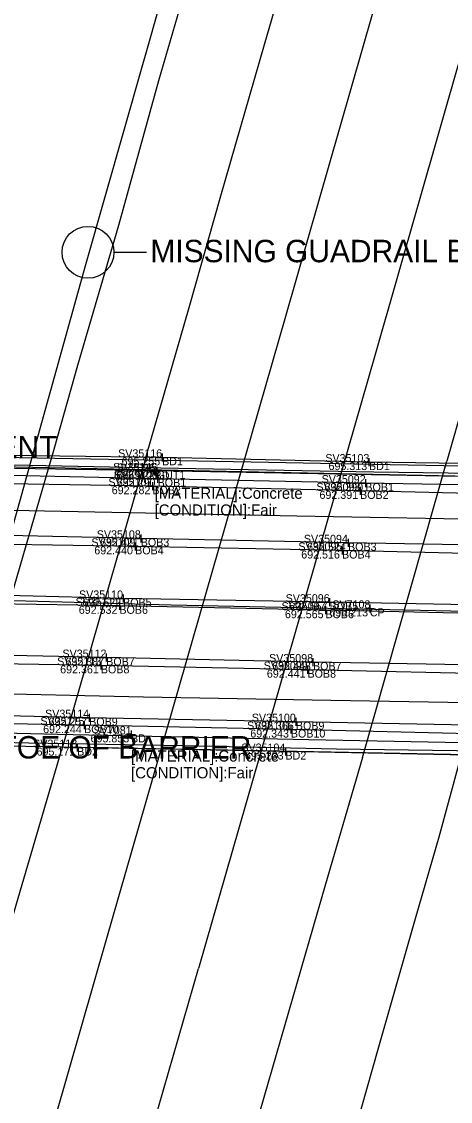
# Model space of a CAD drawing. Extents: x 1659932 to 1663108, y 619867 to 620611.
# Drawn here: x 1661299.3 to 1661352.9, y 620170.2 to 620305.2 of the extents above; entities that cross this region are included whole.
import ezdxf

# ---------------------------------------------------------------- set-up
doc = ezdxf.new("R2010")
doc.units = 0
for name, color, linetype in [('BR_X_Rail_Object', 7, 'Continuous'), ('BR_X_SV_Bottom_of_Beam', 7, 'Continuous'), ('BR_X_SV_Bottom_of_Beam_Text', 7, 'Continuous'), ('BR_X_SV_Deck_Top', 7, 'Continuous'), ('BR_X_SV_Deck_Top_Text', 7, 'Continuous'), ('PM_X_CL_Double_Solid', 7, 'Continuous'), ('PM_X_Edge_Line', 7, 'Continuous'), ('PM_X_Lane_Line', 7, 'Continuous'), ('PV_X_Curb', 7, 'Continuous'), ('PV_X_EOP', 7, 'Continuous'), ('RD_X_GR_Rt', 7, 'Continuous'), ('SC_Scratch6', 7, 'Continuous'), ('SV_X_Break_Lines', 7, 'Continuous'), ('SV_X_Shot_Marker', 7, 'Continuous'), ('SV_X_Text', 7, 'Continuous'), ('SV_X_Text_Comment', 7, 'Continuous'), ('SV_X_Text_Elevation', 7, 'Continuous'), ('SV_X_Text_Name', 7, 'Continuous')]:
    doc.layers.add(name, color=color, linetype=linetype)

msp = doc.modelspace()

# ---------------------------------------------------------------- linework, layer by layer
at = {"layer": 'BR_X_Rail_Object'}
for points in [[(1661456.59, 620247.69), (1661443.63, 620247.91), (1661428.53, 620248.27), (1661413.14, 620248.51), (1661400.82, 620248.72), (1661386.31, 620249), (1661374.13, 620249.21), (1661358.77, 620249.51), (1661343.2, 620249.8), (1661327.99, 620250.09), (1661312.41, 620250.4), (1661292.25, 620250.78)], [(1661292.27, 620249.91), (1661312.35, 620249.47), (1661327.66, 620249.2), (1661343.36, 620248.92), (1661358.83, 620248.69), (1661374.6, 620248.4), (1661387.62, 620248.08), (1661401.06, 620247.89), (1661413.42, 620247.71), (1661428.46, 620247.39), (1661443.69, 620247.11), (1661456.88, 620246.85)], [(1661277.09, 620215.16), (1661299.83, 620214.64), (1661320.76, 620214.23), (1661340.16, 620213.86), (1661357.27, 620213.54), (1661379.28, 620213.13), (1661397.22, 620212.74), (1661415.21, 620212.37), (1661433.51, 620212.02), (1661450.82, 620211.69)], [(1661450.15, 620212.16), (1661434.35, 620212.46), (1661415.69, 620212.76), (1661398.09, 620213.11), (1661378.82, 620213.5), (1661356.68, 620213.98), (1661338.69, 620214.25), (1661319.51, 620214.68), (1661300.2, 620215), (1661277.5, 620215.53)]]:
    msp.add_lwpolyline(points, dxfattribs=at)
at = {"layer": 'BR_X_SV_Bottom_of_Beam'}
for points in [[(1661517.58, 620243.01), (1661496.9, 620243.44), (1661470.92, 620243.84), (1661445.09, 620244.44), (1661419.15, 620244.95), (1661393.26, 620245.42), (1661367.36, 620245.92), (1661341.63, 620246.52), (1661315.65, 620247.11), (1661289.75, 620247.52), (1661264.38, 620248.32), (1661238.2, 620248.61)], [(1661523.4, 620243.85), (1661497.42, 620244.38), (1661471.69, 620244.95), (1661445.77, 620245.45), (1661419.9, 620245.97), (1661394.01, 620246.51), (1661368.15, 620247.03), (1661342.29, 620247.49), (1661316.31, 620248.04), (1661290.56, 620248.6), (1661264.65, 620249.03), (1661238.6, 620249.58)], [(1661521.26, 620236.36), (1661495.33, 620236.96), (1661469.49, 620237.51), (1661443.57, 620238), (1661417.71, 620238.51), (1661391.88, 620239.08), (1661365.99, 620239.56), (1661340.12, 620240.03), (1661314.2, 620240.59), (1661288.35, 620241.15), (1661262.48, 620241.61), (1661236.62, 620242.15)], [(1661520.6, 620235.45), (1661494.63, 620235.97), (1661468.71, 620236.38), (1661442.94, 620237), (1661417.1, 620237.51), (1661391.1, 620237.98), (1661365.2, 620238.45), (1661339.37, 620239.07), (1661313.5, 620239.59), (1661287.59, 620239.99), (1661261.72, 620240.63), (1661235.91, 620241.14)], [(1661519.08, 620228.95), (1661493.23, 620229.44), (1661467.37, 620230.03), (1661441.42, 620230.57), (1661415.6, 620231.07), (1661389.73, 620231.65), (1661363.82, 620232.13), (1661337.82, 620232.61), (1661311.99, 620233.08), (1661286.18, 620233.72), (1661260.33, 620234.13), (1661234.38, 620234.66)], [(1661518.51, 620227.98), (1661492.53, 620228.47), (1661466.56, 620228.95), (1661440.74, 620229.56), (1661414.82, 620230.07), (1661388.94, 620230.52), (1661363.07, 620231.02), (1661337.3, 620231.61), (1661311.53, 620232.16), (1661285.45, 620232.59), (1661259.59, 620233.14), (1661233.67, 620233.67)], [(1661516.94, 620221.49), (1661491.08, 620222.02), (1661465.19, 620222.58), (1661439.25, 620223.09), (1661413.44, 620223.61), (1661387.58, 620224.17), (1661361.7, 620224.66), (1661335.74, 620225.13), (1661309.88, 620225.69), (1661284.01, 620226.24), (1661258.16, 620226.7), (1661232.1, 620227.23)], [(1661516.25, 620220.54), (1661490.62, 620220.91), (1661464.53, 620221.45), (1661438.64, 620222.1), (1661412.71, 620222.61), (1661386.76, 620223.07), (1661360.95, 620223.56), (1661335.05, 620224.18), (1661309.21, 620224.72), (1661283.27, 620225.13), (1661257.54, 620225.69), (1661231.6, 620226.26)], [(1661514.76, 620214.06), (1661488.91, 620214.55), (1661463.02, 620215.15), (1661437.13, 620215.62), (1661411.26, 620216.17), (1661385.43, 620216.69), (1661359.54, 620217.18), (1661333.6, 620217.68), (1661307.75, 620218.18), (1661281.89, 620218.77), (1661255.86, 620219.28), (1661229.67, 620219.8)], [(1661514.07, 620213.08), (1661488.21, 620213.6), (1661462.26, 620214.04), (1661436.51, 620214.64), (1661410.52, 620215.17), (1661384.6, 620215.6), (1661358.81, 620216.08), (1661332.97, 620216.7), (1661307.11, 620217.25), (1661281.1, 620217.69), (1661255.32, 620218.27), (1661229.46, 620218.85)]]:
    msp.add_lwpolyline(points, dxfattribs=at)
at = {"layer": 'BR_X_SV_Deck_Top'}
for points in [[(1661524.15, 620246.52), (1661498.29, 620247.07), (1661472.43, 620247.6), (1661446.52, 620248.07), (1661420.55, 620248.6), (1661394.77, 620249.02), (1661368.93, 620249.74), (1661342.74, 620250.12), (1661316.87, 620250.71), (1661291.25, 620251.01), (1661265.13, 620251.8)], [(1661513.53, 620210.29), (1661487.66, 620211.1), (1661461.66, 620211.35), (1661435.63, 620211.89), (1661409.96, 620212.42), (1661383.84, 620212.93), (1661332.3, 620213.95), (1661306.25, 620214.44), (1661280.43, 620214.97), (1661254.73, 620215.77)]]:
    msp.add_lwpolyline(points, dxfattribs=at)
at = {"layer": 'PM_X_CL_Double_Solid'}
msp.add_lwpolyline([(1661546.99, 620228), (1661534.02, 620228.31), (1661515.7, 620228.67), (1661490.63, 620229.2), (1661465.72, 620229.57), (1661443.89, 620229.92), (1661424.27, 620230.22), (1661405.8, 620230.53), (1661384.67, 620230.88), (1661362.57, 620231.27), (1661341.51, 620231.74), (1661317.99, 620232.23), (1661293.69, 620232.89), (1661270.17, 620233.35), (1661246.4, 620233.83), (1661221.68, 620234.26), (1661205.71, 620234.62)], dxfattribs=at)
at = {"layer": 'PM_X_Edge_Line'}
for p, q in [((1661314.92, 620250.98), (1661304.26, 620213.97)), ((1661341.94, 620213.22), (1661352.49, 620250.24))]:
    msp.add_line(p, q, dxfattribs=at)
for points in [[(1661314.92, 620250.98), (1661320.24, 620269.45), (1661324.21, 620283.38), (1661329.68, 620302.28), (1661336.02, 620324.07), (1661342.92, 620348.04), (1661349.76, 620372.22), (1661357.79, 620400.47), (1661365.87, 620428.74), (1661375.17, 620461.08), (1661385.4, 620496.29), (1661395.58, 620531), (1661407.96, 620573.95), (1661414.41, 620596.94)], [(1661447.15, 620578.18), (1661442.08, 620560.71), (1661436.66, 620541.93), (1661430.96, 620522.04), (1661424.5, 620499.71), (1661417.8, 620476.46), (1661410.39, 620450.9), (1661399.15, 620411.88), (1661394.24, 620394.79), (1661380.03, 620345.6), (1661374.37, 620326.1), (1661366.48, 620299.21), (1661362.47, 620285.11), (1661357.43, 620267.56), (1661352.49, 620250.24)], [(1661550.12, 620239.2), (1661538.67, 620239.52), (1661512.09, 620240.18), (1661488.88, 620240.66), (1661465.84, 620241.07), (1661441.89, 620241.44), (1661414.82, 620241.89), (1661388.37, 620242.34), (1661361.28, 620242.85), (1661333.71, 620243.37), (1661302.17, 620244), (1661273.35, 620244.59), (1661246.42, 620245.13), (1661216.4, 620245.66), (1661208.5, 620245.81)], [(1661202.2, 620223.59), (1661213.11, 620223.27), (1661228.39, 620222.77), (1661259.55, 620222), (1661275.15, 620221.64), (1661292.52, 620221.27), (1661314.56, 620220.78), (1661337.97, 620220.36), (1661364.83, 620219.9), (1661379.25, 620219.63), (1661405.95, 620219.2), (1661427.48, 620218.87), (1661447.99, 620218.48), (1661471.4, 620218.02), (1661496.02, 620217.59), (1661519.24, 620217.2), (1661540.28, 620216.77), (1661543.97, 620216.72)], [(1661205.76, 619869.48), (1661211.13, 619888.81), (1661217.41, 619910.98), (1661224.34, 619935.2), (1661231.75, 619961.45), (1661235.51, 619974.89), (1661240.67, 619993.15), (1661247.93, 620018.65), (1661255.82, 620046.31), (1661265.01, 620078.44), (1661274.65, 620112.11), (1661283.8, 620143.93), (1661298.65, 620194.91), (1661304.26, 620213.97)], [(1661341.94, 620213.22), (1661337.31, 620197.39), (1661326.5, 620160.05), (1661314.91, 620119.7), (1661309.67, 620101.22), (1661301.86, 620073.85), (1661294.2, 620047.04), (1661286.06, 620018.73), (1661279.32, 619995.43), (1661269.93, 619963.07), (1661260.59, 619930.4), (1661255.64, 619912.95), (1661249.95, 619892.74), (1661243.97, 619871.61)]]:
    msp.add_lwpolyline(points, dxfattribs=at)
at = {"layer": 'PM_X_Lane_Line'}
for p, q in [((1661309.87, 620190.36), (1661332.33, 620268.36)), ((1661343.5, 620263.55), (1661321.42, 620186.85))]:
    msp.add_line(p, q, dxfattribs=at)
for points in [[(1661332.33, 620268.36), (1661343.26, 620306.38), (1661354.65, 620346.19), (1661365.24, 620383.52), (1661376.49, 620422.77), (1661387.47, 620460.99), (1661398.71, 620499.13), (1661410.08, 620538.06), (1661421.21, 620576.86)], [(1661431.96, 620570.3), (1661421.04, 620532.1), (1661410.7, 620495.6), (1661399.42, 620457.06), (1661388.16, 620417.77), (1661377.14, 620379.94), (1661365.7, 620340.36), (1661354.27, 620301.08), (1661343.5, 620263.55)], [(1661221.59, 619881.87), (1661232.5, 619920.16), (1661243.45, 619958.79), (1661254.55, 619998.19), (1661265.28, 620036.08), (1661276.49, 620075.34), (1661287.7, 620113.67), (1661298.9, 620152.14), (1661309.87, 620190.36)], [(1661233.25, 619878.6), (1661244.2, 619917.52), (1661254.62, 619954.7), (1661265.49, 619992.35), (1661276.71, 620030.87), (1661288.27, 620071), (1661299.13, 620109.41), (1661309.52, 620145.68), (1661321.42, 620186.85)]]:
    msp.add_lwpolyline(points, dxfattribs=at)
at = {"layer": 'PV_X_Curb'}
msp.add_lwpolyline([(1661523.34, 620245.12), (1661471.57, 620246.11), (1661446, 620246.6), (1661316.22, 620249.01), (1661290.79, 620249.44), (1661264.95, 620250.25), (1661238.71, 620250.79)], dxfattribs=at)
at = {"layer": 'PV_X_EOP'}
msp.add_line((1661292.37, 620214.09), (1661303.39, 620251.73), dxfattribs=at)
for points in [[(1661303.39, 620251.73), (1661306.32, 620262.23), (1661311.45, 620279.74), (1661316.46, 620297.78), (1661320.54, 620311.85)], [(1661354.07, 620212.76), (1661351.46, 620203.27), (1661348.5, 620193.03), (1661343.86, 620176.72), (1661338.34, 620157.33), (1661329.5, 620126.95), (1661323.43, 620105.42), (1661317.63, 620085.66), (1661309.75, 620058.02), (1661302.02, 620030.69), (1661292.65, 619998.31), (1661288.53, 619983.09), (1661284.46, 619969.78), (1661279.63, 619952.97), (1661274.63, 619935.67), (1661263.8, 619897.55), (1661258.1, 619878.27)]]:
    msp.add_lwpolyline(points, dxfattribs=at)
at = {"layer": 'RD_X_GR_Rt'}
msp.add_line((1661307.3, 620274.78), (1661286.56, 620200.56), dxfattribs=at)
msp.add_lwpolyline([(1661365.74, 620480.35), (1661358.38, 620454.11), (1661351.31, 620429.73), (1661342.87, 620400.4), (1661334.47, 620370.93), (1661319.26, 620316.75), (1661307.3, 620274.78)], dxfattribs=at)
at = {"layer": 'SC_Scratch6'}
msp.add_line((1661310.84, 620276.33), (1661314.93, 620276.33), dxfattribs=at)
msp.add_circle((1661307.6, 620276.33), 3.24, dxfattribs=at)
at = {"layer": 'SV_X_Break_Lines'}
for points in [[(1661238.02, 620250.73), (1661242.29, 620250.67), (1661247.52, 620250.55), (1661257.18, 620250.39), (1661265.86, 620250.2), (1661279.25, 620249.88), (1661300.71, 620249.47), (1661326.88, 620248.93), (1661355.54, 620248.37), (1661388.8, 620247.7), (1661434.33, 620246.78), (1661467.07, 620246.1), (1661484, 620245.72), (1661498.39, 620245.53), (1661509.52, 620245.36), (1661518.82, 620245.07), (1661524.43, 620245.01)], [(1661228.67, 620217.71), (1661237.33, 620217.55), (1661248.53, 620217.33), (1661262.13, 620217.12), (1661283.4, 620216.64), (1661303.8, 620216.14), (1661335.24, 620215.45), (1661384.24, 620214.5), (1661403.67, 620214.09), (1661434.66, 620213.56), (1661466.76, 620212.97), (1661495.66, 620212.45), (1661513.4, 620212.01)]]:
    msp.add_lwpolyline(points, dxfattribs=at)
at = {"layer": 'SV_X_Shot_Marker'}
for p, q in [((1661316.37, 620250.71), (1661317.37, 620250.71)), ((1661316.87, 620251.21), (1661316.87, 620250.21)), ((1661316.87, 620250.71), (1661316.87, 620250.71)), ((1661342.24, 620250.12), (1661343.24, 620250.12)), ((1661342.74, 620250.62), (1661342.74, 620249.62)), ((1661342.74, 620250.12), (1661342.74, 620250.12)), ((1661315.43, 620248.93), (1661316.43, 620248.93)), ((1661315.72, 620249.01), (1661316.72, 620249.01)), ((1661315.93, 620249.43), (1661315.93, 620248.43)), ((1661315.93, 620248.93), (1661315.93, 620248.93)), ((1661316.22, 620249.51), (1661316.22, 620248.51)), ((1661316.22, 620249.01), (1661316.22, 620249.01)), ((1661315.65, 620247.61), (1661315.65, 620246.61)), ((1661315.81, 620248.04), (1661316.81, 620248.04)), ((1661316.31, 620248.54), (1661316.31, 620247.54)), ((1661316.31, 620248.04), (1661316.31, 620248.04)), ((1661341.79, 620247.49), (1661342.79, 620247.49)), ((1661342.29, 620247.99), (1661342.29, 620246.99)), ((1661342.29, 620247.49), (1661342.29, 620247.49)), ((1661315.15, 620247.11), (1661316.15, 620247.11)), ((1661315.65, 620247.11), (1661315.65, 620247.11)), ((1661341.13, 620246.52), (1661342.13, 620246.52)), ((1661341.63, 620247.02), (1661341.63, 620246.02)), ((1661341.63, 620246.52), (1661341.63, 620246.52)), ((1661313.7, 620240.59), (1661314.7, 620240.59)), ((1661314.2, 620241.09), (1661314.2, 620240.09)), ((1661314.2, 620240.59), (1661314.2, 620240.59)), ((1661340.12, 620240.53), (1661340.12, 620239.53)), ((1661313, 620239.59), (1661314, 620239.59)), ((1661313.5, 620240.09), (1661313.5, 620239.09)), ((1661313.5, 620239.59), (1661313.5, 620239.59)), ((1661339.37, 620239.57), (1661339.37, 620238.57)), ((1661339.62, 620240.03), (1661340.62, 620240.03)), ((1661340.12, 620240.03), (1661340.12, 620240.03)), ((1661338.87, 620239.07), (1661339.87, 620239.07)), ((1661339.37, 620239.07), (1661339.37, 620239.07)), ((1661311.49, 620233.08), (1661312.49, 620233.08)), ((1661311.53, 620232.66), (1661311.53, 620231.66)), ((1661311.99, 620233.58), (1661311.99, 620232.58)), ((1661311.99, 620233.08), (1661311.99, 620233.08)), ((1661337.32, 620232.61), (1661338.32, 620232.61)), ((1661337.82, 620233.11), (1661337.82, 620232.11)), ((1661337.82, 620232.61), (1661337.82, 620232.61)), ((1661311.03, 620232.16), (1661312.03, 620232.16)), ((1661311.53, 620232.16), (1661311.53, 620232.16)), ((1661336.8, 620231.61), (1661337.8, 620231.61)), ((1661337.3, 620232.11), (1661337.3, 620231.11)), ((1661337.3, 620231.61), (1661337.3, 620231.61)), ((1661342.35, 620231.84), (1661343.35, 620231.84)), ((1661342.85, 620232.34), (1661342.85, 620231.34)), ((1661342.85, 620231.84), (1661342.85, 620231.84)), ((1661309.38, 620225.69), (1661310.38, 620225.69)), ((1661309.88, 620226.19), (1661309.88, 620225.19)), ((1661309.88, 620225.69), (1661309.88, 620225.69)), ((1661308.71, 620224.72), (1661309.71, 620224.72)), ((1661309.21, 620225.22), (1661309.21, 620224.22)), ((1661309.21, 620224.72), (1661309.21, 620224.72)), ((1661335.05, 620224.68), (1661335.05, 620223.68)), ((1661335.24, 620225.13), (1661336.24, 620225.13)), ((1661335.74, 620225.63), (1661335.74, 620224.63)), ((1661335.74, 620225.13), (1661335.74, 620225.13)), ((1661334.55, 620224.18), (1661335.55, 620224.18)), ((1661335.05, 620224.18), (1661335.05, 620224.18)), ((1661307.11, 620217.75), (1661307.11, 620216.75)), ((1661307.25, 620218.18), (1661308.25, 620218.18)), ((1661307.75, 620218.68), (1661307.75, 620217.68)), ((1661307.75, 620218.18), (1661307.75, 620218.18)), ((1661333.1, 620217.68), (1661334.1, 620217.68)), ((1661333.6, 620218.18), (1661333.6, 620217.18)), ((1661333.6, 620217.68), (1661333.6, 620217.68)), ((1661306.61, 620217.25), (1661307.61, 620217.25)), ((1661307.11, 620217.25), (1661307.11, 620217.25)), ((1661312.98, 620216.6), (1661312.98, 620215.6)), ((1661332.47, 620216.7), (1661333.47, 620216.7)), ((1661332.97, 620217.2), (1661332.97, 620216.2)), ((1661332.97, 620216.7), (1661332.97, 620216.7)), ((1661306.25, 620214.94), (1661306.25, 620213.94)), ((1661312.48, 620216.1), (1661313.48, 620216.1)), ((1661312.98, 620216.1), (1661312.98, 620216.1)), ((1661305.75, 620214.44), (1661306.75, 620214.44)), ((1661306.25, 620214.44), (1661306.25, 620214.44)), ((1661331.8, 620213.95), (1661332.8, 620213.95)), ((1661332.3, 620214.45), (1661332.3, 620213.45)), ((1661332.3, 620213.95), (1661332.3, 620213.95))]:
    msp.add_line(p, q, dxfattribs=at)

# ---------------------------------------------------------------- texts
at = {"layer": 'BR_X_SV_Bottom_of_Beam_Text'}
for s, p in [('SV35106', (1661310.81, 620248.04)), ('SV35107', (1661310.15, 620247.11)), ('692.290', (1661311.2, 620247.05)), ('BOB1', (1661316.31, 620247.05)), ('SV35093', (1661336.17, 620246.52)), ('SV35092', (1661336.82, 620247.49)), ('692.390', (1661337.17, 620246.49)), ('BOB1', (1661342.29, 620246.49)), ('692.282', (1661310.57, 620246.11)), ('BOB2', (1661315.65, 620246.11)), ('692.391', (1661336.55, 620245.52)), ('BOB2', (1661341.63, 620245.52)), ('SV35109', (1661308.02, 620239.59)), ('SV35108', (1661308.7, 620240.59)), ('692.421', (1661309.12, 620239.59)), ('BOB3', (1661314.2, 620239.59)), ('SV35094', (1661334.6, 620240.03)), ('692.440', (1661308.39, 620238.59)), ('BOB4', (1661313.5, 620238.59)), ('SV35095', (1661333.91, 620239.07)), ('692.524', (1661335, 620239.03)), ('BOB3', (1661340.12, 620239.03)), ('692.516', (1661334.27, 620238.07)), ('BOB4', (1661339.37, 620238.07)), ('SV35110', (1661306.48, 620233.08)), ('SV35111', (1661306.05, 620232.16)), ('692.522', (1661306.91, 620232.08)), ('BOB5', (1661311.99, 620232.08)), ('SV35097', (1661331.81, 620231.61)), ('SV35096', (1661332.32, 620232.61)), ('692.557', (1661332.72, 620231.61)), ('BOB5', (1661337.82, 620231.61)), ('692.532', (1661306.45, 620231.16)), ('BOB6', (1661311.53, 620231.16)), ('692.565', (1661332.23, 620230.61)), ('BOB6', (1661337.3, 620230.61)), ('SV35113', (1661303.75, 620224.72)), ('SV35112', (1661304.41, 620225.69)), ('692.387', (1661304.78, 620224.69)), ('BOB7', (1661309.88, 620224.69)), ('SV35098', (1661330.25, 620225.13)), ('692.361', (1661304.12, 620223.72)), ('BOB8', (1661309.21, 620223.72)), ('SV35099', (1661329.57, 620224.18)), ('692.448', (1661330.64, 620224.13)), ('BOB7', (1661335.74, 620224.13)), ('692.441', (1661329.97, 620223.18)), ('BOB8', (1661335.05, 620223.18)), ('SV35114', (1661302.24, 620218.18)), ('SV35115', (1661301.65, 620217.25)), ('692.257', (1661302.66, 620217.18)), ('BOB9', (1661307.75, 620217.18)), ('SV35101', (1661327.49, 620216.7)), ('SV35100', (1661328.09, 620217.68)), ('692.366', (1661328.5, 620216.68)), ('BOB9', (1661333.6, 620216.68)), ('692.244', (1661301.99, 620216.25)), ('BOB10', (1661307.11, 620216.25)), ('692.343', (1661327.9, 620215.7)), ('BOB10', (1661332.97, 620215.7))]:
    msp.add_text(s, height=1, dxfattribs=at).set_placement(p)
at = {"layer": 'BR_X_SV_Deck_Top_Text'}
for s, p in [('SV35116', (1661311.37, 620250.71)), ('695.255', (1661311.8, 620249.71)), ('BD1', (1661316.87, 620249.71)), ('SV35103', (1661337.28, 620250.12)), ('695.313', (1661337.68, 620249.12)), ('BD1', (1661342.74, 620249.12)), ('695.912', (1661310.85, 620247.93)), ('SV7096', (1661311.22, 620248.93)), ('BD', (1661315.93, 620247.93)), ('SV7081', (1661308.3, 620216.1)), ('SV35118', (1661300.75, 620214.44)), ('695.853', (1661307.92, 620215.1)), ('BD', (1661312.98, 620215.1)), ('SV35104', (1661326.78, 620213.95)), ('695.171', (1661301.17, 620213.44)), ('BD2', (1661306.25, 620213.44)), ('695.233', (1661327.23, 620212.95)), ('BD2', (1661332.3, 620212.95))]:
    msp.add_text(s, height=1, dxfattribs=at).set_placement(p)
at = {"layer": 'SC_Scratch6'}
for s, p in [('MISSING GUADRAIL BEYOND THIS', (1661315.4, 620275.09)), ('MISSING OUTLINE OF ABUTMENT', (1661242.83, 620250.59)), ('MISSING TOE OF BARRIER', (1661279.56, 620213.08))]:
    msp.add_text(s, height=2.8, dxfattribs=at).set_placement(p)
at = {"layer": 'SV_X_Text'}
for s, p in [('[MATERIAL]:Concrete', (1661315.93, 620245.53)), ('[CONDITION]:Fair', (1661315.93, 620243.43)), ('[MATERIAL]:Concrete', (1661312.98, 620212.7)), ('[CONDITION]:Fair', (1661312.98, 620210.6))]:
    msp.add_text(s, height=1.4, dxfattribs=at).set_placement(p)
at = {"layer": 'SV_X_Text_Comment'}
for s, p in [('GUT1', (1661316.22, 620248.01)), ('CP', (1661342.85, 620230.84))]:
    msp.add_text(s, height=1, dxfattribs=at).set_placement(p)
at = {"layer": 'SV_X_Text_Elevation'}
for s, p in [('696.022', (1661311.15, 620248.01)), ('696.213', (1661337.79, 620230.84))]:
    msp.add_text(s, height=1, dxfattribs=at).set_placement(p)
at = {"layer": 'SV_X_Text_Name'}
for s, p in [('SV35145', (1661310.75, 620249.01)), ('SV7108', (1661338.16, 620231.84))]:
    msp.add_text(s, height=1, dxfattribs=at).set_placement(p)

doc.saveas('drawing.dxf')
